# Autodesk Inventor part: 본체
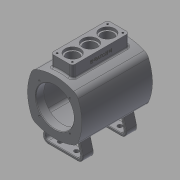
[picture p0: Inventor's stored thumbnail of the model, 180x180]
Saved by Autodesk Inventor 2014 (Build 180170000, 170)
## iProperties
Created: 2015-11
Part Number: 본체
Material: 일반
Document SubType Name: Modeling
Designer: mduedu
Density: 2.71 g/cm^3
Appearance: 기본값
Author: mduedu
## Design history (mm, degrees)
sketch "스케치2"
  geometry: L1 (0, 250)-(0, -250); L2 (250, 0)-(-250, 0); L3 (-50, 50)-(50, 50); L4 (50, 50)-(50, -50); L5 (50, -50)-(-50, -50); L6 (-50, -50)-(-50, 50); A1 r 90 centre (-40, 0) between (40.415, -40.415) and (40.415, 40.415); A2 r 90 centre (40, 0) between (-40.415, 40.415) and (-40.415, -40.415); A3 r 90 centre (0, -40) between (40.415, 40.415) and (-40.415, 40.415); A4 r 90 centre (0, 40) between (-40.415, -40.415) and (40.415, -40.415); 2 further points
  constraints: 12 end point, 8 point on circle, 4 centre point, 4 tangent, 3 perpendicular, 2 horizontal alignment, 2 midpoint, 2 parallel, 2 symmetric about line, 1 coincident, 1 equal radius, 1 horizontal, 1 vertical, 1 vertical alignment, 2 other
  dimensions: "d6" = 500 distance of L1.start L1.end; "d8" = 500 distance of L2.start L2.end; "d9" = 100 distance of L3.end L4.end; "d11" = 90 radius of A3
extrude "돌출1" new body sketch "스케치2" stored distance "d12" = 130; taper "d13" = 0 deg
fillet "모깎기6" dims "d30" = 15
feature "쉘1" dims "d31" = 15, "d32" = 6, "d33" = 15
sketch "스케치5"
  geometry: C1 r 35 at (0, 0); 1 further point
  constraints: 1 centre point, 1 coincident
  dimensions: "d34" = 70 diameter of C1
extrude "돌출3" cut sketch "스케치5" stored distance "d36" = 3; taper "d37" = 0 deg
fillet "모깎기14" dims "d78" = 3
sketch "스케치12"
  geometry: L1 (0, 0)-(28.284, 28.284); L2 (0, 0)-(40, 0); A1 r 40 centre (0, 0) between (28.284, 28.284) and (40, 0); 2 further points
  constraints: 4 end point, 2 coincident, 2 point on circle, 1 centre point, 1 horizontal
  dimensions: "d79" = 80 diameter of A1; "d80" = 45 deg angle of L2 L1
hole "구멍2" sketch "스케치12" at (28.284, 28.284) diameter "d82" = 3.242; stored, may be unused: countersink angle "d86" = 90 deg, drill point angle "d88" = 118 deg; dims "d83" = 9, "d84" = 10, "d85" = 2, "d87" = 11
node "작업 평면2"
sketch "스케치13"
  geometry: L1 (-52.5, -20)-(52.5, -20); L2 (52.5, -20)-(52.5, 20); L3 (52.5, 20)-(-52.5, 20); L4 (-52.5, 20)-(-52.5, -20); L5 (-52.5, -20)-(52.5, 20); L6 (52.5, -20)-(-52.5, 20); 1 further point
  constraints: 12 end point, 2 midpoint, 2 parallel, 1 horizontal, 1 perpendicular
  dimensions: "d93" = 105 distance of L2.end L3.end; "d95" = 40 distance of L1.end L2.end
extrude "돌출8" join sketch "스케치13" stored distance "d96" = 80; taper "d97" = 0 deg
fillet "모깎기15" dims "d98" = 5
fillet "모깎기16" dims "d99" = 3
sketch "스케치14"
  geometry: L1 (-52.5, 15)-(-52.5, -15) reference; L2 (52.5, -15)-(52.5, 15) reference; L3 (-52.5, 0)-(52.5, 0); 4 further points
  constraints: 2 end point, 2 midpoint, 2 point on line, 1 coincident
  dimensions: "d100" = 32 distance of point (-32, 0) point (0, 0); "d102" = 32 distance of point (32, 0) point (0, 0) (derived)
hole "구멍3" sketch "스케치14" at (-32, 0), (0, 0), (32, 0) diameter "d103" = 22; stored, may be unused: countersink angle "d107" = 90 deg, drill point angle "d109" = 118 deg; dims "d104" = 8, "d105" = 28, "d106" = 5, "d108" = 10
sketch "스케치15"
  geometry: L1 (46.5, -14)-(-46.5, -14); L2 (-46.5, -14)-(-46.5, 14); L3 (-46.5, 14)-(46.5, 14); L4 (46.5, 14)-(46.5, -14); L5 (46.5, -14)-(-46.5, 14); L6 (-46.5, -14)-(46.5, 14); L7 (47.5, 20)-(-47.5, 20) reference; L8 (-52.5, 15)-(-52.5, -15) reference; 5 further points
  constraints: 12 end point, 4 coincident, 2 midpoint, 2 parallel, 1 horizontal, 1 perpendicular
  dimensions: "d110" = 6 distance between parallel lines of L3 L7; "d111" = 6 distance between parallel lines of L2 L8
hole "구멍4" sketch "스케치15" at (-46.5, 14), (46.5, 14), (46.5, -14), (-46.5, -14) diameter "d112" = 3.242; stored, may be unused: countersink angle "d116" = 90 deg, drill point angle "d118" = 118 deg; dims "d113" = 10, "d114" = 28, "d115" = 5, "d117" = 13
sketch "스케치16"
  geometry: L1 (33.5, 0)-(61.5, 0) reference; 2 further points
  constraints: 1 vertical alignment, 1 other
  dimensions: "d128" = 11 distance from line of L1 point (47.5, -11)
feature "엠보싱2" sketch "스케치16" dims "d6" = 500, "d8" = 500, "d9" = 100, "d11" = 90, "d34" = 70, "d123" = 0.5, "d124" = 0
chamfer "모따기1" distance "d125" = 1; stored, may be unused: second distance "d126" = 2, angle "d127" = 45 deg
sketch "스케치18"
  geometry: L1 (0, 0)-(0, -80); L2 (40, -80)-(30.531, -44.663); L3 (-40, -80)-(-30.531, -44.663); L4 (-40, -80)-(40, -80); A1 r 90 centre (0, 40) between (-34.941, -42.941) and (34.941, -42.941) reference; A2 r 90 centre (0, 40) between (-30.531, -44.663) and (30.531, -44.663)
  constraints: 8 end point, 3 point on circle, 2 symmetric about line, 1 centre point, 1 coincident, 1 midpoint, 1 perpendicular, 1 vertical
  dimensions: "d132" = 80 distance of L3.start L2.start; "d134" = 75 deg angle of L4 L2; "d136" = 80 distance of L1.start L1.end
extrude "돌출9" new body sketch "스케치18" stored distance "d137" = 100; taper "d138" = 0 deg
fillet "모깎기17" dims "d139" = 10
sketch "스케치19"
  geometry: L1 (26.968, -80)-(-26.968, -80) reference; L2 (-36.627, -67.412)-(-30.531, -44.663) reference; L3 (30.531, -44.663)-(36.627, -67.412) reference; L4 (-25.775, -46.23)-(-31.797, -68.706); L5 (-26.968, -75)-(26.968, -75); L6 (31.797, -68.706)-(25.775, -46.23); L7 (0, 0)-(0, -80); A1 r 10 centre (26.968, -70) between (26.968, -80) and (36.627, -67.412) reference; A2 r 10 centre (-26.968, -70) between (-36.627, -67.412) and (-26.968, -80) reference; A3 r 90 centre (0, 40) between (-30.531, -44.663) and (30.531, -44.663) reference; A4 r 5 centre (-26.968, -70) between (-31.797, -68.706) and (-26.968, -75); A5 r 5 centre (26.968, -70) between (26.968, -75) and (31.797, -68.706); A6 r 90 centre (0, 40) between (-25.775, -46.23) and (25.775, -46.23)
  constraints: 8 end point, 7 point on circle, 3 centre point, 2 parallel, 1 coincident, 1 midpoint, 1 symmetric about line, 1 tangent, 2 other
  dimensions: "d140" = 5 distance between parallel lines of L1 L5
extrude "돌출10" cut sketch "스케치19" stored distance "d141" = 100; taper "d142" = 0 deg
sketch "스케치20"
  geometry: L1 (-30, 0)-(30, 0); L2 (30, 0)-(30, -90); L3 (30, -90)-(-30, -90); L4 (-30, -90)-(-30, 0); L5 (50, -80)-(-50, -80) reference; 2 further points
  constraints: 8 end point, 2 parallel, 1 coincident, 1 horizontal, 1 midpoint, 1 perpendicular
  dimensions: "d143" = 10 distance from line of L5 L2.end; "d144" = 60 distance of L2.end L3.end
extrude "돌출11" cut sketch "스케치20" stored distance "d145" = 100; taper "d146" = 0 deg
sketch "스케치21"
  geometry: L1 (0, 26.968)-(100, 26.968); L2 (100, 53.935)-(100, 0) reference; L3 (0, 0)-(0, 53.935) reference; L4 (0, 53.935)-(20, 53.935) reference; L5 (20, 0)-(0, 0) reference; L6 (115, 76.968)-(-15, 76.968) reference; L7 (115, -23.032)-(-15, -23.032) reference; L8 (10, 53.935)-(10, 0); L9 (50, 76.968)-(50, -23.032); C1 r 4 at (10, 41.968); C2 r 4 at (10, 11.968); C3 r 4 at (90, 41.968); C4 r 4 at (90, 11.968); 2 further points
  constraints: 6 end point, 6 midpoint, 4 centre point, 3 symmetric about line, 1 coincident, 1 horizontal, 1 point on line, 3 other
  dimensions: "d147" = 8 diameter of C1; "d148" = 15 distance from line of C1.centre L1
extrude "돌출12" cut sketch "스케치21" stored distance "d149" = 100; taper "d150" = 0 deg
feature "결합2"
  node "솔리드3"
fillet "모깎기18" dims "d151" = 1
fillet "모깎기19" dims "d152" = 2
node "솔리드1"
pattern_circular "원형 패턴1" dims angle "d90" = 360 deg
mirror "대칭3"
node "투영된 루프1"
